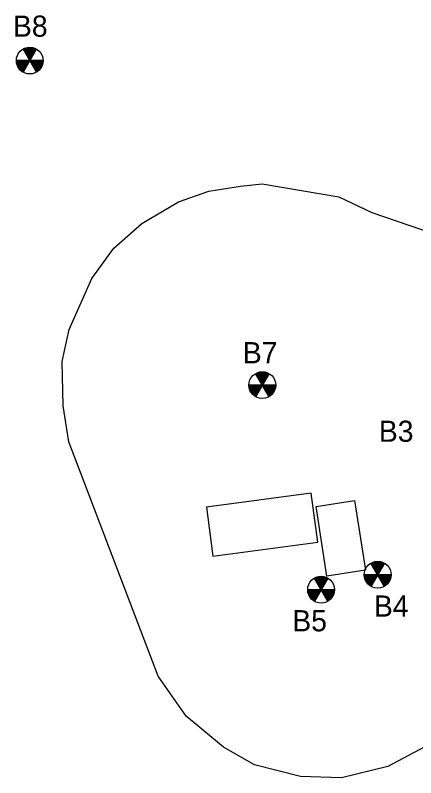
# Model space of a CAD drawing. Extents: x 1640347 to 1640460, y 843798 to 843906.
# Drawn here: x 1640347.3 to 1640404, y 843797.7 to 843905.7 of the extents above; entities that cross this region are included whole.
import ezdxf

# ---------------------------------------------------------------- set-up
doc = ezdxf.new("R2010")
doc.units = 0
for name, color, linetype in [('Boring Cell', 7, 'Continuous'), ('Exist Contamination Known - Area-Soil', 7, 'Continuous'), ('Exist Underground Storage Tank - Outline', 7, 'Continuous')]:
    doc.layers.add(name, color=color, linetype=linetype)

msp = doc.modelspace()

# ---------------------------------------------------------------- linework, layer by layer
at = {"layer": 'Boring Cell'}
for p, q in [((1640350.31, 843897.6), (1640348.41, 843900.88)), ((1640350.31, 843900.88), (1640348.41, 843897.6)), ((1640351.25, 843899.24), (1640347.46, 843899.24)), ((1640383.25, 843851.63), (1640381.35, 843854.91)), ((1640383.25, 843854.91), (1640381.35, 843851.63)), ((1640384.2, 843853.27), (1640380.41, 843853.27)), ((1640399.59, 843824.76), (1640397.69, 843828.05)), ((1640399.59, 843828.05), (1640397.69, 843824.76)), ((1640391.58, 843822.66), (1640389.68, 843825.95)), ((1640391.58, 843825.95), (1640389.68, 843822.66)), ((1640400.54, 843826.41), (1640396.75, 843826.41)), ((1640392.53, 843824.3), (1640388.73, 843824.3))]:
    msp.add_line(p, q, dxfattribs=at)
for centre in [(1640349.36, 843899.24), (1640382.3, 843853.27), (1640398.64, 843826.41), (1640390.63, 843824.3)]:
    msp.add_circle(centre, 1.9, dxfattribs=at)
for centre, radius, start, end in [((1640349.36, 843899.24), 1.84, 60, 120), ((1640349.36, 843899.24), 1.78, 60, 120), ((1640349.36, 843899.24), 1.72, 60, 120), ((1640349.36, 843899.24), 1.66, 60, 120), ((1640349.36, 843899.24), 1.6, 60, 120), ((1640349.36, 843899.24), 1.54, 60, 120), ((1640349.36, 843899.24), 1.48, 60, 120), ((1640349.36, 843899.24), 1.42, 60, 120), ((1640349.36, 843899.24), 1.36, 60, 120), ((1640349.36, 843899.24), 1.3, 60, 120), ((1640349.36, 843899.24), 1.24, 60, 120), ((1640349.36, 843899.24), 1.18, 60, 120), ((1640349.36, 843899.24), 1.12, 60, 120), ((1640349.36, 843899.24), 1.06, 60, 120), ((1640349.36, 843899.24), 0.997, 60, 120), ((1640349.36, 843899.24), 0.937, 60, 120), ((1640349.36, 843899.24), 0.877, 60, 120), ((1640349.36, 843899.24), 0.817, 60, 120), ((1640349.36, 843899.24), 0.757, 60, 120), ((1640349.36, 843899.24), 0.697, 60, 120), ((1640349.36, 843899.24), 0.637, 60, 120), ((1640349.36, 843899.24), 0.577, 60, 120), ((1640349.36, 843899.24), 0.517, 60, 120), ((1640349.36, 843899.24), 0.457, 60, 120), ((1640349.36, 843899.24), 0.397, 60, 120), ((1640349.36, 843899.24), 0.337, 60, 120), ((1640349.36, 843899.24), 0.277, 60, 120), ((1640349.36, 843899.24), 0.217, 60, 120), ((1640349.36, 843899.24), 0.157, 60, 120), ((1640349.36, 843899.24), 1.84, 180, 240), ((1640349.36, 843899.24), 1.78, 180, 240), ((1640349.36, 843899.24), 1.72, 180, 240), ((1640349.36, 843899.24), 1.66, 180, 240), ((1640349.36, 843899.24), 1.6, 180, 240), ((1640349.36, 843899.24), 1.54, 180, 240), ((1640349.36, 843899.24), 1.48, 180, 240), ((1640349.36, 843899.24), 1.42, 180, 240), ((1640349.36, 843899.24), 1.36, 180, 240), ((1640349.36, 843899.24), 1.3, 180, 240), ((1640349.36, 843899.24), 1.24, 180, 240), ((1640349.36, 843899.24), 1.18, 180, 240), ((1640349.36, 843899.24), 1.12, 180, 240), ((1640349.36, 843899.24), 1.06, 180, 240), ((1640349.36, 843899.24), 0.997, 180, 240), ((1640349.36, 843899.24), 0.937, 180, 240), ((1640349.36, 843899.24), 0.877, 180, 240), ((1640349.36, 843899.24), 0.817, 180, 240), ((1640349.36, 843899.24), 0.757, 180, 240), ((1640349.36, 843899.24), 0.697, 180, 240), ((1640349.36, 843899.24), 0.637, 180, 240), ((1640349.36, 843899.24), 0.577, 180, 240), ((1640349.36, 843899.24), 0.517, 180, 240), ((1640349.36, 843899.24), 0.457, 180, 240), ((1640349.36, 843899.24), 0.397, 180, 240), ((1640349.36, 843899.24), 0.337, 180, 240), ((1640349.36, 843899.24), 0.277, 180, 240), ((1640349.36, 843899.24), 0.217, 180, 240), ((1640349.36, 843899.24), 0.157, 180, 240), ((1640349.36, 843899.24), 0.0972, 180, 240), ((1640349.36, 843899.24), 0.0972, 60, 120), ((1640349.36, 843899.24), 0.0972, 300, 0), ((1640349.36, 843899.24), 0.157, 300, 0), ((1640349.36, 843899.24), 0.217, 300, 0), ((1640349.36, 843899.24), 0.277, 300, 0), ((1640349.36, 843899.24), 0.337, 300, 360), ((1640349.36, 843899.24), 0.397, 300, 0), ((1640349.36, 843899.24), 0.457, 300, 360), ((1640349.36, 843899.24), 0.517, 300, 0), ((1640349.36, 843899.24), 0.577, 300, 0), ((1640349.36, 843899.24), 0.637, 300, 0), ((1640349.36, 843899.24), 0.697, 300, 0), ((1640349.36, 843899.24), 0.757, 300, 0), ((1640349.36, 843899.24), 0.817, 300, 0), ((1640349.36, 843899.24), 0.877, 300, 0), ((1640349.36, 843899.24), 0.937, 300, 0), ((1640349.36, 843899.24), 0.997, 300, 0), ((1640349.36, 843899.24), 1.06, 300, 0), ((1640349.36, 843899.24), 1.12, 300, 0), ((1640349.36, 843899.24), 1.18, 300, 0), ((1640349.36, 843899.24), 1.24, 300, 360), ((1640349.36, 843899.24), 1.3, 300, 0), ((1640349.36, 843899.24), 1.36, 300, 0), ((1640349.36, 843899.24), 1.42, 300, 0), ((1640349.36, 843899.24), 1.48, 300, 0), ((1640349.36, 843899.24), 1.54, 300, 0), ((1640349.36, 843899.24), 1.6, 300, 0), ((1640349.36, 843899.24), 1.66, 300, 360), ((1640349.36, 843899.24), 1.72, 300, 0), ((1640349.36, 843899.24), 1.78, 300, 0), ((1640349.36, 843899.24), 1.84, 300, 0), ((1640382.3, 843853.27), 1.84, 60, 120), ((1640382.3, 843853.27), 1.78, 60, 120), ((1640382.3, 843853.27), 1.72, 60, 120), ((1640382.3, 843853.27), 1.66, 60, 120), ((1640382.3, 843853.27), 1.6, 60, 120), ((1640382.3, 843853.27), 1.54, 60, 120), ((1640382.3, 843853.27), 1.48, 60, 120), ((1640382.3, 843853.27), 1.42, 60, 120), ((1640382.3, 843853.27), 1.36, 60, 120), ((1640382.3, 843853.27), 1.3, 60, 120), ((1640382.3, 843853.27), 1.24, 60, 120), ((1640382.3, 843853.27), 1.18, 60, 120), ((1640382.3, 843853.27), 1.12, 60, 120), ((1640382.3, 843853.27), 1.06, 60, 120), ((1640382.3, 843853.27), 0.997, 60, 120), ((1640382.3, 843853.27), 0.937, 60, 120), ((1640382.3, 843853.27), 0.877, 60, 120), ((1640382.3, 843853.27), 0.817, 60, 120), ((1640382.3, 843853.27), 0.757, 60, 120), ((1640382.3, 843853.27), 1.84, 180, 240), ((1640382.3, 843853.27), 1.78, 180, 240), ((1640382.3, 843853.27), 1.72, 180, 240), ((1640382.3, 843853.27), 1.66, 180, 240), ((1640382.3, 843853.27), 1.6, 180, 240), ((1640382.3, 843853.27), 1.54, 180, 240), ((1640382.3, 843853.27), 1.48, 180, 240), ((1640382.3, 843853.27), 1.42, 180, 240), ((1640382.3, 843853.27), 1.36, 180, 240), ((1640382.3, 843853.27), 1.3, 180, 240), ((1640382.3, 843853.27), 1.24, 180, 240), ((1640382.3, 843853.27), 1.18, 180, 240), ((1640382.3, 843853.27), 1.12, 180, 240), ((1640382.3, 843853.27), 1.06, 180, 240), ((1640382.3, 843853.27), 0.997, 180, 240), ((1640382.3, 843853.27), 0.937, 180, 240), ((1640382.3, 843853.27), 0.877, 180, 240), ((1640382.3, 843853.27), 0.817, 180, 240), ((1640382.3, 843853.27), 0.757, 180, 240), ((1640382.3, 843853.27), 0.697, 180, 240), ((1640382.3, 843853.27), 0.637, 180, 240), ((1640382.3, 843853.27), 0.577, 180, 240), ((1640382.3, 843853.27), 0.517, 180, 240), ((1640382.3, 843853.27), 0.457, 180, 240), ((1640382.3, 843853.27), 0.397, 180, 240), ((1640382.3, 843853.27), 0.697, 60, 120), ((1640382.3, 843853.27), 0.337, 180, 240), ((1640382.3, 843853.27), 0.637, 60, 120), ((1640382.3, 843853.27), 0.577, 60, 120), ((1640382.3, 843853.27), 0.277, 180, 240), ((1640382.3, 843853.27), 0.517, 60, 120), ((1640382.3, 843853.27), 0.457, 60, 120), ((1640382.3, 843853.27), 0.217, 180, 240), ((1640382.3, 843853.27), 0.397, 60, 120), ((1640382.3, 843853.27), 0.337, 60, 120), ((1640382.3, 843853.27), 0.157, 180, 240), ((1640382.3, 843853.27), 0.277, 60, 120), ((1640382.3, 843853.27), 0.217, 60, 120), ((1640382.3, 843853.27), 0.0972, 180, 240), ((1640382.3, 843853.27), 0.157, 60, 120), ((1640382.3, 843853.27), 0.0972, 60, 120), ((1640382.3, 843853.27), 0.0972, 300, 0), ((1640382.3, 843853.27), 0.157, 300, 0), ((1640382.3, 843853.27), 0.217, 300, 0), ((1640382.3, 843853.27), 0.277, 300, 0), ((1640382.3, 843853.27), 0.337, 300, 360), ((1640382.3, 843853.27), 0.397, 300, 0), ((1640382.3, 843853.27), 0.457, 300, 360), ((1640382.3, 843853.27), 0.517, 300, 0), ((1640382.3, 843853.27), 0.577, 300, 0), ((1640382.3, 843853.27), 0.637, 300, 0), ((1640382.3, 843853.27), 0.697, 300, 0), ((1640382.3, 843853.27), 0.757, 300, 0), ((1640382.3, 843853.27), 0.817, 300, 0), ((1640382.3, 843853.27), 0.877, 300, 0), ((1640382.3, 843853.27), 0.937, 300, 0), ((1640382.3, 843853.27), 0.997, 300, 0), ((1640382.3, 843853.27), 1.06, 300, 0), ((1640382.3, 843853.27), 1.12, 300, 0), ((1640382.3, 843853.27), 1.18, 300, 0), ((1640382.3, 843853.27), 1.24, 300, 360), ((1640382.3, 843853.27), 1.3, 300, 0), ((1640382.3, 843853.27), 1.36, 300, 0), ((1640382.3, 843853.27), 1.42, 300, 0), ((1640382.3, 843853.27), 1.48, 300, 0), ((1640382.3, 843853.27), 1.54, 300, 0), ((1640382.3, 843853.27), 1.6, 300, 0), ((1640382.3, 843853.27), 1.66, 300, 360), ((1640382.3, 843853.27), 1.72, 300, 0), ((1640382.3, 843853.27), 1.78, 300, 0), ((1640382.3, 843853.27), 1.84, 300, 0), ((1640398.64, 843826.41), 1.84, 60, 120), ((1640398.64, 843826.41), 1.78, 60, 120), ((1640398.64, 843826.41), 1.72, 60, 120), ((1640398.64, 843826.41), 1.66, 60, 120), ((1640398.64, 843826.41), 1.6, 60, 120), ((1640398.64, 843826.41), 1.54, 60, 120), ((1640398.64, 843826.41), 1.48, 60, 120), ((1640398.64, 843826.41), 1.42, 60, 120), ((1640398.64, 843826.41), 1.36, 60, 120), ((1640398.64, 843826.41), 1.3, 60, 120), ((1640398.64, 843826.41), 1.24, 60, 120), ((1640398.64, 843826.41), 1.18, 60, 120), ((1640398.64, 843826.41), 1.12, 60, 120), ((1640398.64, 843826.41), 1.06, 60, 120), ((1640398.64, 843826.41), 0.997, 60, 120), ((1640398.64, 843826.41), 0.937, 60, 120), ((1640398.64, 843826.41), 0.877, 60, 120), ((1640398.64, 843826.41), 0.817, 60, 120), ((1640398.64, 843826.41), 0.757, 60, 120), ((1640398.64, 843826.41), 0.697, 60, 120), ((1640398.64, 843826.41), 0.637, 60, 120), ((1640390.63, 843824.3), 1.84, 60, 120), ((1640390.63, 843824.3), 1.78, 60, 120), ((1640390.63, 843824.3), 1.72, 60, 120), ((1640390.63, 843824.3), 1.66, 60, 120), ((1640398.64, 843826.41), 1.84, 180, 240), ((1640398.64, 843826.41), 1.78, 180, 240), ((1640398.64, 843826.41), 1.72, 180, 240), ((1640398.64, 843826.41), 1.66, 180, 240), ((1640398.64, 843826.41), 1.6, 180, 240), ((1640398.64, 843826.41), 1.54, 180, 240), ((1640398.64, 843826.41), 1.48, 180, 240), ((1640398.64, 843826.41), 1.42, 180, 240), ((1640398.64, 843826.41), 1.36, 180, 240), ((1640398.64, 843826.41), 1.3, 180, 240), ((1640398.64, 843826.41), 1.24, 180, 240), ((1640398.64, 843826.41), 1.18, 180, 240), ((1640398.64, 843826.41), 1.12, 180, 240), ((1640398.64, 843826.41), 1.06, 180, 240), ((1640398.64, 843826.41), 0.997, 180, 240), ((1640398.64, 843826.41), 0.937, 180, 240), ((1640398.64, 843826.41), 0.877, 180, 240), ((1640398.64, 843826.41), 0.817, 180, 240), ((1640398.64, 843826.41), 0.757, 180, 240), ((1640398.64, 843826.41), 0.697, 180, 240), ((1640398.64, 843826.41), 0.637, 180, 240), ((1640398.64, 843826.41), 0.577, 180, 240), ((1640398.64, 843826.41), 0.517, 180, 240), ((1640398.64, 843826.41), 0.457, 180, 240), ((1640398.64, 843826.41), 0.397, 180, 240), ((1640398.64, 843826.41), 0.337, 180, 240), ((1640398.64, 843826.41), 0.577, 60, 120), ((1640398.64, 843826.41), 0.277, 180, 240), ((1640398.64, 843826.41), 0.517, 60, 120), ((1640398.64, 843826.41), 0.457, 60, 120), ((1640398.64, 843826.41), 0.217, 180, 240), ((1640398.64, 843826.41), 0.397, 60, 120), ((1640398.64, 843826.41), 0.337, 60, 120), ((1640398.64, 843826.41), 0.157, 180, 240), ((1640398.64, 843826.41), 0.277, 60, 120), ((1640398.64, 843826.41), 0.217, 60, 120), ((1640398.64, 843826.41), 0.0972, 180, 240), ((1640398.64, 843826.41), 0.157, 60, 120), ((1640398.64, 843826.41), 0.0972, 60, 120), ((1640398.64, 843826.41), 0.0972, 300, 0), ((1640398.64, 843826.41), 0.157, 300, 0), ((1640398.64, 843826.41), 0.217, 300, 0), ((1640398.64, 843826.41), 0.277, 300, 0), ((1640398.64, 843826.41), 0.337, 300, 360), ((1640398.64, 843826.41), 0.397, 300, 0), ((1640398.64, 843826.41), 0.457, 300, 360), ((1640398.64, 843826.41), 0.517, 300, 0), ((1640398.64, 843826.41), 0.577, 300, 0), ((1640398.64, 843826.41), 0.637, 300, 0), ((1640398.64, 843826.41), 0.697, 300, 0), ((1640398.64, 843826.41), 0.757, 300, 0), ((1640398.64, 843826.41), 0.817, 300, 0), ((1640398.64, 843826.41), 0.877, 300, 0), ((1640398.64, 843826.41), 0.937, 300, 0), ((1640398.64, 843826.41), 0.997, 300, 0), ((1640398.64, 843826.41), 1.06, 300, 0), ((1640398.64, 843826.41), 1.12, 300, 0), ((1640398.64, 843826.41), 1.18, 300, 0), ((1640398.64, 843826.41), 1.24, 300, 360), ((1640398.64, 843826.41), 1.3, 300, 0), ((1640398.64, 843826.41), 1.36, 300, 0), ((1640398.64, 843826.41), 1.42, 300, 0), ((1640398.64, 843826.41), 1.48, 300, 0), ((1640398.64, 843826.41), 1.54, 300, 0), ((1640398.64, 843826.41), 1.6, 300, 0), ((1640398.64, 843826.41), 1.66, 300, 360), ((1640398.64, 843826.41), 1.72, 300, 0), ((1640398.64, 843826.41), 1.78, 300, 0), ((1640398.64, 843826.41), 1.84, 300, 0), ((1640390.63, 843824.3), 1.6, 60, 120), ((1640390.63, 843824.3), 1.54, 60, 120), ((1640390.63, 843824.3), 1.48, 60, 120), ((1640390.63, 843824.3), 1.42, 60, 120), ((1640390.63, 843824.3), 1.36, 60, 120), ((1640390.63, 843824.3), 1.3, 60, 120), ((1640390.63, 843824.3), 1.24, 60, 120), ((1640390.63, 843824.3), 1.18, 60, 120), ((1640390.63, 843824.3), 1.12, 60, 120), ((1640390.63, 843824.3), 1.06, 60, 120), ((1640390.63, 843824.3), 0.997, 60, 120), ((1640390.63, 843824.3), 0.937, 60, 120), ((1640390.63, 843824.3), 0.877, 60, 120), ((1640390.63, 843824.3), 0.817, 60, 120), ((1640390.63, 843824.3), 0.757, 60, 120), ((1640390.63, 843824.3), 0.697, 60, 120), ((1640390.63, 843824.3), 0.637, 60, 120), ((1640390.63, 843824.3), 0.577, 60, 120), ((1640390.63, 843824.3), 1.84, 180, 240), ((1640390.63, 843824.3), 1.78, 180, 240), ((1640390.63, 843824.3), 1.72, 180, 240), ((1640390.63, 843824.3), 1.66, 180, 240), ((1640390.63, 843824.3), 1.6, 180, 240), ((1640390.63, 843824.3), 1.54, 180, 240), ((1640390.63, 843824.3), 1.48, 180, 240), ((1640390.63, 843824.3), 1.42, 180, 240), ((1640390.63, 843824.3), 1.36, 180, 240), ((1640390.63, 843824.3), 1.3, 180, 240), ((1640390.63, 843824.3), 1.24, 180, 240), ((1640390.63, 843824.3), 1.18, 180, 240), ((1640390.63, 843824.3), 1.12, 180, 240), ((1640390.63, 843824.3), 1.06, 180, 240), ((1640390.63, 843824.3), 0.997, 180, 240), ((1640390.63, 843824.3), 0.937, 180, 240), ((1640390.63, 843824.3), 0.877, 180, 240), ((1640390.63, 843824.3), 0.817, 180, 240), ((1640390.63, 843824.3), 0.757, 180, 240), ((1640390.63, 843824.3), 0.697, 180, 240), ((1640390.63, 843824.3), 0.637, 180, 240), ((1640390.63, 843824.3), 0.577, 180, 240), ((1640390.63, 843824.3), 0.517, 180, 240), ((1640390.63, 843824.3), 0.457, 180, 240), ((1640390.63, 843824.3), 0.397, 180, 240), ((1640390.63, 843824.3), 0.337, 180, 240), ((1640390.63, 843824.3), 0.277, 180, 240), ((1640390.63, 843824.3), 0.517, 60, 120), ((1640390.63, 843824.3), 0.457, 60, 120), ((1640390.63, 843824.3), 0.217, 180, 240), ((1640390.63, 843824.3), 0.397, 60, 120), ((1640390.63, 843824.3), 0.337, 60, 120), ((1640390.63, 843824.3), 0.157, 180, 240), ((1640390.63, 843824.3), 0.277, 60, 120), ((1640390.63, 843824.3), 0.217, 60, 120), ((1640390.63, 843824.3), 0.0972, 180, 240), ((1640390.63, 843824.3), 0.157, 60, 120), ((1640390.63, 843824.3), 0.0972, 60, 120), ((1640390.63, 843824.3), 0.0972, 300, 0), ((1640390.63, 843824.3), 0.157, 300, 0), ((1640390.63, 843824.3), 0.217, 300, 0), ((1640390.63, 843824.3), 0.277, 300, 0), ((1640390.63, 843824.3), 0.337, 300, 360), ((1640390.63, 843824.3), 0.397, 300, 0), ((1640390.63, 843824.3), 0.457, 300, 360), ((1640390.63, 843824.3), 0.517, 300, 0), ((1640390.63, 843824.3), 0.577, 300, 0), ((1640390.63, 843824.3), 0.637, 300, 0), ((1640390.63, 843824.3), 0.697, 300, 0), ((1640390.63, 843824.3), 0.757, 300, 0), ((1640390.63, 843824.3), 0.817, 300, 0), ((1640390.63, 843824.3), 0.877, 300, 0), ((1640390.63, 843824.3), 0.937, 300, 0), ((1640390.63, 843824.3), 0.997, 300, 0), ((1640390.63, 843824.3), 1.06, 300, 0), ((1640390.63, 843824.3), 1.12, 300, 0), ((1640390.63, 843824.3), 1.18, 300, 0), ((1640390.63, 843824.3), 1.24, 300, 360), ((1640390.63, 843824.3), 1.3, 300, 0), ((1640390.63, 843824.3), 1.36, 300, 0), ((1640390.63, 843824.3), 1.42, 300, 0), ((1640390.63, 843824.3), 1.48, 300, 0), ((1640390.63, 843824.3), 1.54, 300, 0), ((1640390.63, 843824.3), 1.6, 300, 0), ((1640390.63, 843824.3), 1.66, 300, 360), ((1640390.63, 843824.3), 1.72, 300, 0), ((1640390.63, 843824.3), 1.78, 300, 0), ((1640390.63, 843824.3), 1.84, 300, 0)]:
    msp.add_arc(centre, radius, start, end, dxfattribs=at)
at = {"layer": 'Exist Contamination Known - Area-Soil'}
msp.add_lwpolyline([(1640406.04, 843802.41), (1640400.07, 843799.26), (1640393.52, 843797.66), (1640387.73, 843797.86), (1640381.18, 843799.48), (1640376.82, 843801.98), (1640371.53, 843806.4), (1640367.54, 843812.03), (1640354.9, 843845.23), (1640354.09, 843850.35), (1640353.96, 843856.64), (1640354.96, 843861.13), (1640358.14, 843868.36), (1640361.25, 843872.66), (1640365.23, 843876.18), (1640370.41, 843879.21), (1640374.71, 843880.76), (1640379.22, 843881.46), (1640382.3, 843881.77), (1640393.14, 843879.92), (1640397.83, 843877.74), (1640418.76, 843870.54)], dxfattribs=at)
at = {"layer": 'Exist Underground Storage Tank - Outline'}
for points in [[(1640389.24, 843837.98), (1640374.38, 843835.97), (1640375.31, 843829.04), (1640390.18, 843831.04)], [(1640396.9, 843827.04), (1640391.46, 843826.21), (1640389.95, 843836.1), (1640395.38, 843836.93)]]:
    msp.add_lwpolyline(points, close=True, dxfattribs=at)

# ---------------------------------------------------------------- texts
at = {"layer": 'Boring Cell'}
for s, p in [('B8', (1640346.98, 843902.62)), ('B7', (1640379.54, 843856.36)), ('B3', (1640398.81, 843845.24)), ('B4', (1640398.11, 843820.48)), ('B5', (1640386.55, 843818.4))]:
    msp.add_text(s, height=3, dxfattribs=at).set_placement(p)

doc.saveas('drawing.dxf')
